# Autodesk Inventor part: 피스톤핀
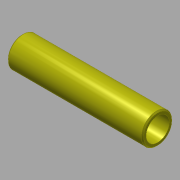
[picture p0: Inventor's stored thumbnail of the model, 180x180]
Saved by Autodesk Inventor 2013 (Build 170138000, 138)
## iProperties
Created: 2016-11
Part Number: 피스톤핀
Material: 강철, 탄소
Document SubType Name: Modeling
Designer: mduedu
Density: 1 g/cm^3
Author: mduedu
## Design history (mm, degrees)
sketch "스케치1"
  geometry: C1 r 5 at (0, 0); C2 r 6.5 at (0, 0); 1 further point
  constraints: 2 centre point, 2 coincident
  dimensions: "d0" = 10 diameter of C1; "d1" = 13 diameter of C2
extrude "돌출1" new body sketch "스케치1" stored distance "d2" = 58; taper "d3" = 0 deg
chamfer "모따기1" distance "d4" = 0.5; stored, may be unused: second distance "d5" = 2, angle "d6" = 45 deg
node "솔리드1"
